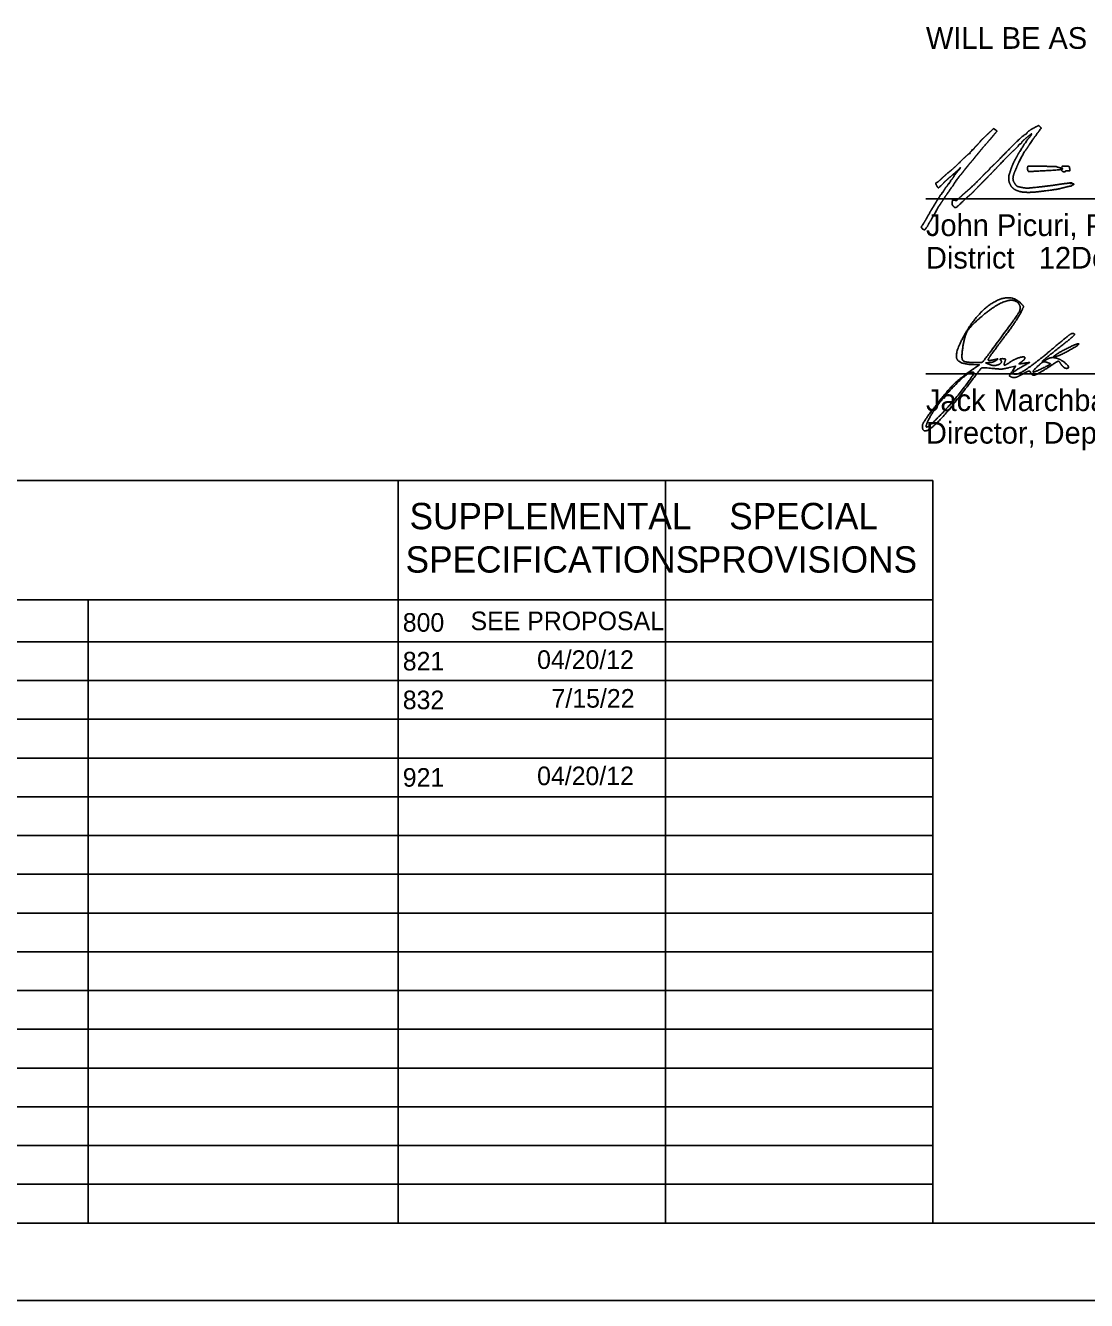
# Model space of a CAD drawing. Extents: x -10 to 89.7, y -4.8 to 22.
# Drawn here: x 18.85 to 25.69, y 0 to 8.23 of the extents above; entities that cross this region are included whole.
import ezdxf

# ---------------------------------------------------------------- set-up
doc = ezdxf.new("R2010")
doc.units = 0
for name, color, linetype in [('GM_X_Minor_Lake', 7, 'Continuous'), ('GM_X_Minor_River', 7, 'Continuous'), ('GM_X_Minor_River_Text', 7, 'Continuous'), ('SH_Text', 7, 'Continuous')]:
    doc.layers.add(name, color=color, linetype=linetype)

msp = doc.modelspace()

# ---------------------------------------------------------------- linework, layer by layer
at = {"layer": 'GM_X_Minor_Lake'}
for p, q in [((24.6564, 7.1081), (28.1564, 7.1081)), ((24.6564, 5.9786), (28.1564, 5.9786)), ((11.25, 5.2917), (24.7, 5.2917)), ((21.25, 0.5), (21.25, 5.2917)), ((22.975, 0.5), (22.975, 5.2917)), ((24.7, 0.5), (24.7, 5.2917)), ((11.25, 4.5209), (24.7, 4.5209)), ((19.25, 0.5), (19.25, 4.5209)), ((11.25, 4.25), (24.7, 4.25)), ((11.25, 4), (24.7, 4)), ((11.25, 3.75), (24.7, 3.75)), ((11.25, 3.5), (24.7, 3.5)), ((11.25, 3.25), (24.7, 3.25)), ((11.25, 3), (24.7, 3)), ((11.25, 2.75), (24.7, 2.75)), ((11.25, 2.5), (24.7, 2.5)), ((11.25, 2.25), (24.7, 2.25)), ((11.25, 2), (24.7, 2)), ((11.25, 1.75), (24.7, 1.75)), ((11.25, 1.5), (24.7, 1.5)), ((11.25, 1.25), (24.7, 1.25)), ((11.25, 1), (24.7, 1)), ((11.25, 0.75), (24.7, 0.75))]:
    msp.add_line(p, q, dxfattribs=at)
at = {"layer": 'GM_X_Minor_River'}
msp.add_lwpolyline([(1.5, 21.5), (33.5, 21.5), (33.5, 0.5), (1.5, 0.5)], close=True, dxfattribs=at)
at = {"layer": 'GM_X_Minor_River_Text'}
for p, q in [((25.3128, 7.2941), (25.3128, 7.2941)), ((25.5357, 7.2872), (25.5357, 7.2872)), ((24.8314, 7.0617), (24.8314, 7.0617)), ((24.6404, 6.9102), (24.6404, 6.9102)), ((25.1187, 6.1837), (25.1187, 6.1837)), ((25.484, 6.0938), (25.484, 6.0938)), ((25.4393, 6.0522), (25.4393, 6.0522))]:
    msp.add_line(p, q, dxfattribs=at)
for points in [[(25.0813, 7.5506), (25.0921, 7.5613), (25.1017, 7.5555)], [(24.8753, 7.3032), (24.8786, 7.3096), (24.8723, 7.3032)], [(25.4055, 7.318), (25.3149, 7.3185), (25.3122, 7.3105)], [(25.5573, 7.3187), (25.5355, 7.3192), (25.5326, 7.3055)], [(25.571, 7.2888), (25.5858, 7.2888), (25.5841, 7.3019)], [(24.9711, 6.0167), (25.0018, 6.038), (24.9639, 6.0386)], [(25.214, 5.9969), (25.2352, 6.0292), (25.1935, 6.0192)]]:
    msp.add_lwpolyline(points, dxfattribs=at)
for points in [[(25.3066, 7.5301), (25.3066, 7.5353), (25.3326, 7.5545), (25.3587, 7.5685)], [(25.3587, 7.5685), (25.3813, 7.5805), (25.3864, 7.5806), (25.3961, 7.5689)], [(25.3961, 7.5689), (25.3996, 7.5647), (25.3994, 7.5629), (25.395, 7.5581)], [(25.009, 7.4807), (25.009, 7.4819), (25.0228, 7.4957), (25.0397, 7.5114)], [(25.0666, 7.4872), (25.0553, 7.4751), (25.0244, 7.4397), (25.0137, 7.4264)], [(25.0397, 7.5114), (25.0566, 7.5272), (25.0753, 7.5448), (25.0813, 7.5506)], [(25.0841, 7.5082), (25.0771, 7.4994), (25.0692, 7.49), (25.0666, 7.4872)], [(25.1041, 7.532), (25.1002, 7.5276), (25.0912, 7.5169), (25.0841, 7.5082)], [(25.1017, 7.5555), (25.1133, 7.5487), (25.1139, 7.5427), (25.1041, 7.532)], [(25.1273, 7.3603), (25.1976, 7.4339), (25.2896, 7.5221), (25.2984, 7.5243)], [(25.2473, 7.3891), (25.2592, 7.4114), (25.3146, 7.4959), (25.3212, 7.5016)], [(25.2901, 7.4894), (25.2816, 7.482), (25.2747, 7.4748), (25.2746, 7.4734)], [(25.3386, 7.527), (25.3386, 7.5292), (25.3136, 7.5098), (25.2901, 7.4894)], [(25.2984, 7.5243), (25.3029, 7.5254), (25.3066, 7.528), (25.3066, 7.5301)], [(25.3212, 7.5016), (25.3258, 7.5057), (25.3386, 7.5244), (25.3386, 7.527)], [(25.3666, 7.5175), (25.3585, 7.5085), (25.3553, 7.504), (25.3289, 7.4648)], [(25.3706, 7.5246), (25.3706, 7.5231), (25.3688, 7.52), (25.3666, 7.5175)], [(25.3802, 7.5375), (25.3749, 7.5318), (25.3706, 7.526), (25.3706, 7.5246)], [(25.3898, 7.55), (25.3898, 7.5487), (25.3855, 7.5431), (25.3802, 7.5375)], [(25.395, 7.5581), (25.3922, 7.5549), (25.3898, 7.5513), (25.3898, 7.55)], [(24.9405, 7.4032), (24.9395, 7.4042), (24.9422, 7.4082), (24.9465, 7.4122)], [(24.9465, 7.4122), (24.9507, 7.4161), (24.9535, 7.4201), (24.9526, 7.421)], [(24.9526, 7.421), (24.9517, 7.4219), (24.9539, 7.4236), (24.9576, 7.4247)], [(24.9576, 7.4247), (24.9612, 7.4259), (24.9642, 7.428), (24.9642, 7.4293)], [(24.9642, 7.4293), (24.9642, 7.4307), (24.9743, 7.4423), (24.9866, 7.4552)], [(24.9866, 7.4552), (24.9989, 7.4681), (25.009, 7.4796), (25.009, 7.4807)], [(25.0137, 7.4264), (25.0073, 7.4185), (24.9973, 7.4063), (24.9916, 7.3992)], [(25.2228, 7.42), (25.2208, 7.42), (25.1901, 7.3889), (25.1204, 7.3162)], [(25.2585, 7.4592), (25.2584, 7.4563), (25.2253, 7.42), (25.2228, 7.42)], [(25.3003, 7.4232), (25.2934, 7.4167), (25.2539, 7.3408), (25.241, 7.3096)], [(25.262, 7.4616), (25.2601, 7.4616), (25.2586, 7.4605), (25.2585, 7.4592)], [(25.2746, 7.4734), (25.2746, 7.4696), (25.266, 7.4616), (25.262, 7.4616)], [(25.3289, 7.4648), (25.3141, 7.4428), (25.3012, 7.4241), (25.3003, 7.4232)], [(24.8068, 7.2817), (24.8241, 7.2959), (24.8581, 7.3275), (24.8993, 7.3679)], [(24.8993, 7.3679), (24.9159, 7.3841), (24.9323, 7.3982), (24.9358, 7.3994)], [(24.9303, 7.3256), (24.9234, 7.3168), (24.917, 7.3089), (24.916, 7.308)], [(24.9465, 7.3448), (24.9445, 7.3431), (24.9372, 7.3344), (24.9303, 7.3256)], [(24.9358, 7.3994), (24.9394, 7.4005), (24.9415, 7.4022), (24.9405, 7.4032)], [(24.9656, 7.3672), (24.9571, 7.3567), (24.9485, 7.3466), (24.9465, 7.3448)], [(24.9916, 7.3992), (24.9858, 7.3922), (24.9741, 7.3778), (24.9656, 7.3672)], [(25.0865, 7.3209), (25.0974, 7.3305), (25.1158, 7.3483), (25.1273, 7.3603)], [(25.2026, 7.292), (25.2076, 7.3084), (25.226, 7.3514), (25.2327, 7.3624)], [(25.2327, 7.3624), (25.2344, 7.3651), (25.2409, 7.3771), (25.2473, 7.3891)], [(24.7537, 7.2353), (24.775, 7.2555), (24.7807, 7.2605), (24.8068, 7.2817)], [(24.8138, 7.2504), (24.8006, 7.2392), (24.7817, 7.2219), (24.7719, 7.212)], [(24.8723, 7.3032), (24.8605, 7.2913), (24.8379, 7.2709), (24.8138, 7.2504)], [(24.8179, 7.2286), (24.8295, 7.2405), (24.8397, 7.257), (24.8376, 7.2604)], [(24.8799, 7.2626), (24.8732, 7.2559), (24.833, 7.1995), (24.833, 7.1968)], [(24.8376, 7.2604), (24.8362, 7.2627), (24.8366, 7.2634), (24.8386, 7.2621)], [(24.8386, 7.2621), (24.8404, 7.261), (24.8444, 7.264), (24.8476, 7.2689)], [(24.8476, 7.2689), (24.8507, 7.2737), (24.8574, 7.2819), (24.8626, 7.2872)], [(24.8626, 7.2872), (24.8677, 7.2925), (24.8734, 7.2997), (24.8753, 7.3032)], [(24.8992, 7.2866), (24.8909, 7.2757), (24.8822, 7.2649), (24.8799, 7.2626)], [(24.916, 7.308), (24.9151, 7.3071), (24.9075, 7.2975), (24.8992, 7.2866)], [(24.941, 7.1752), (24.9537, 7.1863), (24.9993, 7.2316), (25.0253, 7.2588)], [(25.0253, 7.2588), (25.0352, 7.2692), (25.0485, 7.2819), (25.0549, 7.2872)], [(25.1204, 7.3162), (25.0952, 7.2899), (25.0595, 7.2531), (25.041, 7.2343)], [(25.0549, 7.2872), (25.0613, 7.2925), (25.0666, 7.2982), (25.0666, 7.3)], [(25.0666, 7.3), (25.0666, 7.3018), (25.0756, 7.3112), (25.0865, 7.3209)], [(25.1961, 7.2084), (25.1909, 7.2204), (25.1898, 7.2557), (25.1943, 7.2671)], [(25.1943, 7.2671), (25.196, 7.2711), (25.1997, 7.2823), (25.2026, 7.292)], [(25.2328, 7.2904), (25.2199, 7.2629), (25.2167, 7.2269), (25.2258, 7.2127)], [(25.241, 7.3096), (25.2381, 7.3026), (25.2344, 7.2939), (25.2328, 7.2904)], [(25.3122, 7.3105), (25.3107, 7.3059), (25.3109, 7.299), (25.3128, 7.2941)], [(25.3128, 7.2941), (25.3167, 7.284), (25.3197, 7.2838), (25.4122, 7.2888)], [(25.4998, 7.3152), (25.4978, 7.3164), (25.4554, 7.3177), (25.4055, 7.318)], [(25.4122, 7.2888), (25.5138, 7.2943), (25.5507, 7.3016), (25.5169, 7.3096)], [(25.5169, 7.3096), (25.5095, 7.3114), (25.5018, 7.3139), (25.4998, 7.3152)], [(25.5326, 7.3055), (25.5301, 7.2937), (25.5305, 7.2912), (25.5357, 7.2872)], [(25.5357, 7.2872), (25.5427, 7.2819), (25.5562, 7.2809), (25.5562, 7.2856)], [(25.5562, 7.2856), (25.5562, 7.2874), (25.5629, 7.2888), (25.571, 7.2888)], [(25.5807, 7.3166), (25.5798, 7.3175), (25.5693, 7.3184), (25.5573, 7.3187)], [(25.5841, 7.3019), (25.5831, 7.3091), (25.5816, 7.3157), (25.5807, 7.3166)], [(24.7259, 7.1927), (24.7194, 7.2051), (24.7197, 7.2112), (24.7268, 7.2134)], [(24.7719, 7.212), (24.7408, 7.1806), (24.7337, 7.1776), (24.7259, 7.1927)], [(24.7268, 7.2134), (24.73, 7.2145), (24.7421, 7.2243), (24.7537, 7.2353)], [(24.7621, 7.148), (24.7636, 7.148), (24.7685, 7.1549), (24.7732, 7.1634)], [(24.7732, 7.1634), (24.7778, 7.1719), (24.785, 7.1825), (24.7892, 7.1871)], [(24.7892, 7.1871), (24.7934, 7.1916), (24.7977, 7.1976), (24.7988, 7.2005)], [(24.7988, 7.2005), (24.7999, 7.2033), (24.8023, 7.2056), (24.8041, 7.2056)], [(24.8074, 7.1606), (24.8051, 7.1563), (24.8023, 7.1521), (24.8011, 7.1512)], [(24.8041, 7.2056), (24.8059, 7.2056), (24.8074, 7.2078), (24.8074, 7.2104)], [(24.8074, 7.2104), (24.8074, 7.2131), (24.8088, 7.2152), (24.8106, 7.2152)], [(24.8143, 7.1718), (24.8127, 7.17), (24.8096, 7.1649), (24.8074, 7.1606)], [(24.8106, 7.2152), (24.8124, 7.2152), (24.8138, 7.2173), (24.8138, 7.2198)], [(24.8138, 7.2198), (24.8138, 7.2223), (24.8156, 7.2263), (24.8179, 7.2286)], [(24.833, 7.1968), (24.833, 7.1948), (24.8296, 7.1902), (24.8143, 7.1718)], [(24.9111, 7.1492), (24.9215, 7.1582), (24.935, 7.1699), (24.941, 7.1752)], [(24.9778, 7.1698), (24.9616, 7.153), (24.9439, 7.1358), (24.9385, 7.1316)], [(25.041, 7.2343), (25.0225, 7.2156), (24.9941, 7.1866), (24.9778, 7.1698)], [(25.2584, 7.1563), (25.2327, 7.1639), (25.2057, 7.1865), (25.1961, 7.2084)], [(25.2258, 7.2127), (25.2386, 7.1927), (25.2518, 7.1853), (25.2844, 7.1799)], [(25.2844, 7.1799), (25.3051, 7.1765), (25.3165, 7.1769), (25.3722, 7.1829)], [(25.3722, 7.1829), (25.4282, 7.1891), (25.4782, 7.1954), (25.5098, 7.2004)], [(25.5562, 7.1829), (25.5185, 7.1726), (25.4794, 7.1661), (25.385, 7.1544)], [(25.5098, 7.2004), (25.5226, 7.2025), (25.5527, 7.2065), (25.5626, 7.2075)], [(25.5872, 7.1895), (25.5833, 7.1895), (25.5694, 7.1865), (25.5562, 7.1829)], [(25.5626, 7.2075), (25.567, 7.2079), (25.5706, 7.2085), (25.5706, 7.2088)], [(25.5706, 7.2088), (25.5706, 7.2091), (25.5778, 7.2099), (25.5866, 7.2105)], [(25.5866, 7.2105), (25.5983, 7.2114), (25.6005, 7.2109), (25.5946, 7.209)], [(25.5989, 7.1944), (25.5963, 7.1918), (25.591, 7.1896), (25.5872, 7.1895)], [(25.5946, 7.209), (25.5874, 7.2065), (25.5877, 7.2062), (25.5986, 7.2059)], [(25.5986, 7.2059), (25.6052, 7.2058), (25.6106, 7.2042), (25.6106, 7.2024)], [(25.6072, 7.1992), (25.6053, 7.1992), (25.6016, 7.1971), (25.5989, 7.1944)], [(25.6106, 7.2024), (25.6106, 7.2007), (25.6091, 7.1992), (25.6072, 7.1992)], [(24.7048, 7.0587), (24.7218, 7.0874), (24.7295, 7.0999), (24.7367, 7.1109)], [(24.7367, 7.1109), (24.7413, 7.1177), (24.7469, 7.1267), (24.7492, 7.1309)], [(24.7727, 7.1096), (24.7583, 7.0876), (24.7453, 7.0681), (24.7438, 7.0662)], [(24.7492, 7.1309), (24.7515, 7.135), (24.7547, 7.1384), (24.7564, 7.1384)], [(24.7564, 7.1384), (24.758, 7.1384), (24.7594, 7.1406), (24.7594, 7.1432)], [(24.7594, 7.1432), (24.7594, 7.1459), (24.7606, 7.148), (24.7621, 7.148)], [(24.8011, 7.1512), (24.7999, 7.1503), (24.7872, 7.1316), (24.7727, 7.1096)], [(24.8314, 7.0617), (24.8275, 7.0659), (24.8257, 7.0724), (24.8261, 7.0811)], [(24.8261, 7.0811), (24.8268, 7.0989), (24.8287, 7.101), (24.8422, 7.0989)], [(24.9056, 7.1019), (24.858, 7.0561), (24.8435, 7.0483), (24.8314, 7.0617)], [(24.8422, 7.0989), (24.8529, 7.0971), (24.8553, 7.0984), (24.873, 7.1149)], [(24.873, 7.1149), (24.8836, 7.1247), (24.9007, 7.1402), (24.9111, 7.1492)], [(24.9385, 7.1316), (24.9331, 7.1274), (24.9183, 7.1141), (24.9056, 7.1019)], [(25.385, 7.1544), (25.3443, 7.1494), (25.2786, 7.1504), (25.2584, 7.1563)], [(24.6644, 6.9896), (24.6698, 7.0002), (24.6755, 7.0093), (24.6769, 7.0099)], [(24.6769, 7.0099), (24.6783, 7.0105), (24.6794, 7.0127), (24.6794, 7.0148)], [(24.6794, 7.0148), (24.6794, 7.0169), (24.6841, 7.0259), (24.6898, 7.0348)], [(24.6898, 7.0348), (24.6955, 7.0437), (24.7023, 7.0545), (24.7048, 7.0587)], [(24.7157, 7.0176), (24.711, 7.0093), (24.7038, 6.9971), (24.6997, 6.9905)], [(24.7438, 7.0662), (24.7413, 7.0631), (24.737, 7.0557), (24.7157, 7.0176)], [(24.6303, 6.9189), (24.6257, 6.9259), (24.6263, 6.9276), (24.64, 6.9484)], [(24.6404, 6.9102), (24.6375, 6.911), (24.6329, 6.9149), (24.6303, 6.9189)], [(24.64, 6.9484), (24.6479, 6.9605), (24.6589, 6.9791), (24.6644, 6.9896)], [(24.6477, 6.9084), (24.6466, 6.9086), (24.6434, 6.9094), (24.6404, 6.9102)], [(24.673, 6.9446), (24.673, 6.941), (24.6499, 6.908), (24.6477, 6.9084)], [(24.6826, 6.9613), (24.6773, 6.9535), (24.673, 6.946), (24.673, 6.9446)], [(24.6922, 6.977), (24.6922, 6.9762), (24.6879, 6.9691), (24.6826, 6.9613)], [(24.6997, 6.9905), (24.6956, 6.9839), (24.6922, 6.9779), (24.6922, 6.977)], [(24.9074, 6.2344), (24.9937, 6.3848), (25.2018, 6.5009), (25.2674, 6.4352)], [(25.2585, 6.426), (25.2325, 6.468), (25.1064, 6.4269), (25.0111, 6.3452)], [(25.1187, 6.1837), (25.2401, 6.3471), (25.2725, 6.4033), (25.2585, 6.426)], [(25.2674, 6.4352), (25.2862, 6.4164), (25.2863, 6.4114), (25.2679, 6.3729)], [(25.0111, 6.3452), (24.9444, 6.2882), (24.9056, 6.2241), (24.8945, 6.1528)], [(25.2679, 6.3729), (25.257, 6.35), (25.2053, 6.2744), (25.153, 6.205)], [(24.9639, 6.0386), (24.866, 6.0403), (24.8426, 6.1214), (24.9074, 6.2344)], [(24.9726, 6.0518), (25.0193, 6.0518), (25.0238, 6.0559), (25.1187, 6.1837)], [(25.153, 6.205), (25.1008, 6.1357), (25.058, 6.075), (25.058, 6.0702)], [(25.484, 6.0938), (25.5044, 6.1117), (25.6365, 6.1775), (25.6416, 6.1723)], [(25.6416, 6.1723), (25.6478, 6.1661), (25.5052, 6.0893), (25.4875, 6.0893)], [(25.4975, 6.1609), (25.548, 6.2038), (25.5935, 6.239), (25.5986, 6.2391)], [(25.5986, 6.2391), (25.6235, 6.2396), (25.6001, 6.214), (25.5143, 6.1468)], [(24.8945, 6.1528), (24.8831, 6.0795), (24.9045, 6.0518), (24.9726, 6.0518)], [(25.2021, 6.0561), (25.231, 6.0759), (25.2955, 6.0934), (25.2955, 6.0815)], [(25.2362, 5.9768), (25.2593, 5.9768), (25.3853, 6.0656), (25.4975, 6.1609)], [(25.5143, 6.1468), (25.421, 6.0737), (25.3996, 6.0522), (25.4435, 6.0757)], [(25.4875, 6.0893), (25.4827, 6.0893), (25.4812, 6.0913), (25.484, 6.0938)], [(24.7201, 5.7745), (24.7978, 5.875), (24.8779, 5.9523), (24.9711, 6.0167)], [(25.0523, 6.0168), (25.0189, 6.0202), (25.0071, 6.0097), (24.9305, 5.908)], [(25.0643, 6.0512), (25.0419, 6.0503), (25.0423, 6.049), (25.0684, 6.0385)], [(25.1935, 6.0192), (25.1531, 6.0094), (25.1308, 6.009), (25.0523, 6.0168)], [(25.058, 6.0702), (25.058, 6.0655), (25.0735, 6.0651), (25.0924, 6.0695)], [(25.108, 6.0648), (25.0977, 6.0579), (25.078, 6.0517), (25.0643, 6.0512)], [(25.0684, 6.0385), (25.0983, 6.0265), (25.1545, 6.0511), (25.1371, 6.0685)], [(25.0924, 6.0695), (25.1179, 6.0755), (25.1219, 6.0742), (25.108, 6.0648)], [(25.1371, 6.0685), (25.1326, 6.073), (25.1388, 6.0768), (25.151, 6.0768)], [(25.151, 6.0768), (25.1656, 6.0768), (25.1707, 6.0703), (25.166, 6.058)], [(25.166, 6.058), (25.1571, 6.0348), (25.1699, 6.0341), (25.2021, 6.0561)], [(25.2807, 6.0274), (25.2296, 5.9992), (25.2099, 5.9768), (25.2362, 5.9768)], [(25.2739, 6.0574), (25.255, 6.0436), (25.257, 6.0423), (25.2895, 6.0473)], [(25.2955, 6.0815), (25.2955, 6.077), (25.2858, 6.0661), (25.2739, 6.0574)], [(25.2895, 6.0473), (25.3263, 6.0528), (25.3262, 6.0526), (25.2807, 6.0274)], [(25.445, 6.0202), (25.3761, 5.9758), (25.3386, 5.9661), (25.3305, 5.9905)], [(25.3861, 6.0356), (25.3419, 5.9952), (25.3531, 5.9863), (25.4111, 6.0159)], [(25.4393, 6.0522), (25.422, 6.0585), (25.4055, 6.0534), (25.3861, 6.0356)], [(25.4111, 6.0159), (25.4575, 6.0395), (25.4611, 6.0441), (25.4393, 6.0522)], [(25.4435, 6.0757), (25.4561, 6.0824), (25.48, 6.0845), (25.4966, 6.0803)], [(25.5296, 6.0389), (25.5128, 6.063), (25.5108, 6.0626), (25.445, 6.0202)], [(25.4966, 6.0803), (25.5327, 6.0712), (25.5911, 6.0143), (25.5644, 6.0143)], [(25.5644, 6.0143), (25.5548, 6.0143), (25.5391, 6.0254), (25.5296, 6.0389)], [(24.9639, 5.9875), (24.943, 6.0084), (24.7245, 5.7827), (24.6782, 5.6924)], [(24.7483, 5.7111), (24.8159, 5.7802), (24.9716, 5.9798), (24.9639, 5.9875)], [(25.2128, 5.9568), (25.1946, 5.9638), (25.1947, 5.9675), (25.214, 5.9969)], [(25.2794, 5.9767), (25.2538, 5.9615), (25.2238, 5.9526), (25.2128, 5.9568)], [(25.3305, 5.9905), (25.3277, 5.999), (25.3085, 5.9938), (25.2794, 5.9767)], [(24.9305, 5.908), (24.7781, 5.7059), (24.633, 5.5773), (24.633, 5.6443)], [(24.633, 5.6443), (24.633, 5.6539), (24.6722, 5.7125), (24.7201, 5.7745)], [(24.6782, 5.6924), (24.6469, 5.6314), (24.6786, 5.6399), (24.7483, 5.7111)]]:
    msp.add_open_spline(points, degree=2, dxfattribs=at)
at = {"layer": 'SH_Text'}
msp.add_lwpolyline([(0, 0), (34, 0), (34, 22), (0, 22)], close=True, dxfattribs=at)

# ---------------------------------------------------------------- texts
at = {"layer": 'GM_X_Minor_River_Text'}
for s, height, p in [('WILL BE AS SET FORTH BY THE PLANS AND ESTIMATES.', 0.14, (24.6564, 8.0758)), ('John Picuri, P.E., S.I.', 0.14, (24.6564, 6.8681)), ('District       Deputy Director', 0.14, (24.6564, 6.6581)), ('              12', 0.14, (24.6564, 6.6581)), ('Jack Marchbanks, PhD', 0.14, (24.6564, 5.7386)), ('Director, Department of Transportation', 0.14, (24.6564, 5.5286)), ('SUPPLEMENTAL', 0.17, (21.3237, 4.9763)), ('SPECIAL', 0.17, (23.3864, 4.9763)), ('SPECIFICATIONS', 0.17, (21.2982, 4.6963)), ('PROVISIONS', 0.17, (23.1843, 4.6963)), ('SEE PROPOSAL', 0.12, (21.7174, 4.325)), ('800', 0.12, (21.28, 4.315)), ('04/20/12', 0.12, (22.1469, 4.075)), ('821', 0.12, (21.28, 4.065)), ('7/15/22', 0.12, (22.2401, 3.825)), ('832', 0.12, (21.28, 3.815)), ('921', 0.12, (21.28, 3.315)), ('04/20/12', 0.12, (22.1469, 3.325))]:
    msp.add_text(s, height=height, dxfattribs=at).set_placement(p)

doc.saveas('drawing.dxf')
